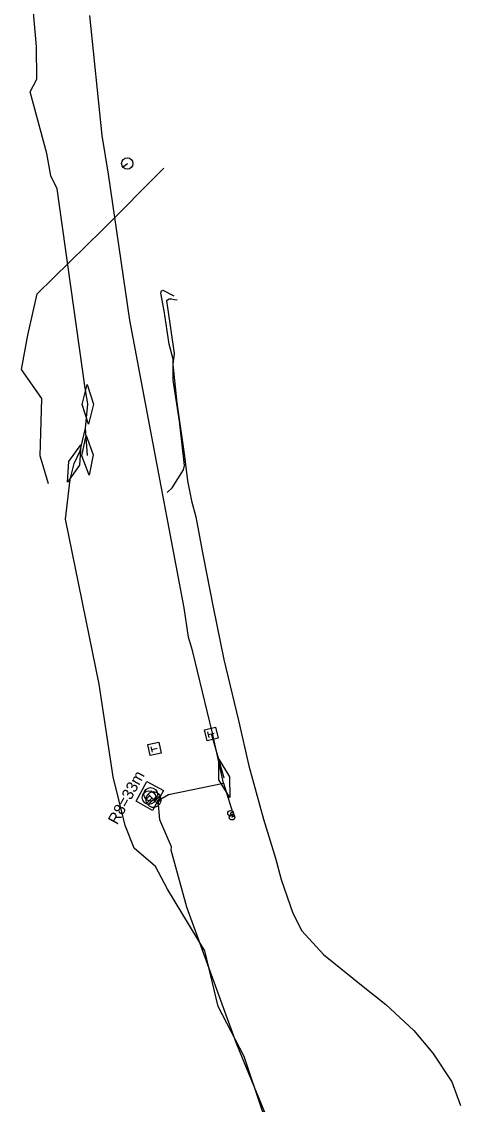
# Model space of a CAD drawing. Extents: x -748507 to -687366, y -1057342 to -1024924.
# Drawn here: x -744476.5 to -744399.1, y -1039770.3 to -1039579.2 of the extents above; entities that cross this region are included whole.
import ezdxf

# ---------------------------------------------------------------- set-up
doc = ezdxf.new("R2010")
doc.units = 0
for name, color, linetype in [('6kV - SŽDC', 7, 'Continuous'), ('DK + TKK - SŽDC', 7, 'Continuous'), ('kanalizace ČD', 7, 'Continuous'), ('PRE - NN', 7, 'Continuous'), ('Sděl MK - SŽDC', 7, 'Continuous'), ('TK+DOK_Pha Holešovice - Kralupy', 7, 'Continuous'), ('Vrstva 42', 7, 'Continuous')]:
    doc.layers.add(name, color=color, linetype=linetype)

msp = doc.modelspace()

# ---------------------------------------------------------------- linework, layer by layer
at = {"layer": '6kV - SŽDC'}
for points in [[(-744471.33, -1039606.37), (-744472.04, -1039602.45), (-744474.97, -1039591.58), (-744473.84, -1039589.36), (-744473.9, -1039583.59), (-744475.42, -1039566.22)], [(-744465.37, -1039643.47), (-744470.25, -1039608.71), (-744471.33, -1039606.37)], [(-744466.19, -1039654.94), (-744465.22, -1039650.95), (-744464.82, -1039646.7), (-744465.37, -1039643.47)], [(-744464.69, -1039650.2), (-744465.82, -1039646.74), (-744464.95, -1039643.2), (-744463.82, -1039646.66), (-744464.69, -1039650.2)], [(-744464.6, -1039659.21), (-744465.86, -1039655.8), (-744465.12, -1039652.23), (-744463.86, -1039655.65), (-744464.6, -1039659.21)], [(-744464.86, -1039655.72), (-744465.22, -1039650.95)], [(-744468.42, -1039660.44), (-744468.18, -1039656.8), (-744466.06, -1039653.84), (-744466.3, -1039657.48), (-744468.42, -1039660.44)], [(-744424.52, -1039793.8), (-744428.32, -1039785.58), (-744432.08, -1039776.07), (-744434.09, -1039771.12), (-744437.21, -1039761.81), (-744441.82, -1039752.98), (-744444.16, -1039743.14), (-744450.73, -1039732.3), (-744452.9, -1039728.3), (-744456.66, -1039725.06), (-744458.25, -1039721.03), (-744460.34, -1039712.48), (-744462.8, -1039696.08), (-744468.74, -1039666.97), (-744467.94, -1039659.97), (-744467.24, -1039657.14), (-744466.19, -1039654.94)]]:
    msp.add_lwpolyline(points, dxfattribs=at)
at = {"layer": 'DK + TKK - SŽDC'}
for p, q in [((-744439.67, -1039718.9), (-744439.57, -1039718.9)), ((-744439.43, -1039719.57), (-744439.33, -1039719.57))]:
    msp.add_line(p, q, dxfattribs=at)
for points in [[(-744447.82, -1039682.66), (-744454.1, -1039649.32), (-744457.43, -1039631.85), (-744461.19, -1039606.07), (-744462.28, -1039599.29), (-744464.47, -1039578.08)], [(-744440.86, -1039713.58), (-744442.82, -1039704.78), (-744446.35, -1039690.15), (-744447.03, -1039687.79), (-744447.82, -1039682.66)], [(-744450.03, -1039724.84), (-744452.09, -1039720.03), (-744452.43, -1039716.64), (-744450.57, -1039715.59), (-744440.86, -1039713.58)], [(-744440.86, -1039713.58), (-744439.27, -1039718.67), (-744438.94, -1039719.36)], [(-744439.27, -1039718.67), (-744439.62, -1039718.9)], [(-744438.94, -1039719.36), (-744439.38, -1039719.57)], [(-744409.27, -1039827.53), (-744414.03, -1039816.04), (-744422.5, -1039800.57), (-744424.03, -1039794.9), (-744438.59, -1039759.5), (-744447.32, -1039735.48), (-744450.1, -1039725.43), (-744450.03, -1039724.84)]]:
    msp.add_lwpolyline(points, dxfattribs=at)
for centre in [(-744439.62, -1039718.9), (-744439.38, -1039719.57)]:
    msp.add_circle(centre, 0.5, dxfattribs=at)
at = {"layer": 'kanalizace ČD'}
msp.add_lwpolyline([(-744458.62, -1039604.83), (-744457.81, -1039604.23)], dxfattribs=at)
msp.add_circle((-744457.85, -1039604.21), 1, dxfattribs=at)
at = {"layer": 'PRE - NN'}
msp.add_lwpolyline([(-744449.05, -1039628.36), (-744449.5, -1039628.26), (-744450.05, -1039628.18), (-744450.46, -1039628.15), (-744450.94, -1039628.48), (-744450.73, -1039629.65), (-744449.61, -1039637.73), (-744449.84, -1039639.66), (-744449.1, -1039646.43), (-744447.74, -1039655.87), (-744447.23, -1039660.21), (-744446.52, -1039663.73), (-744445.76, -1039666.56), (-744444.48, -1039673.5), (-744442.67, -1039682.49), (-744440.8, -1039691.78), (-744438.2, -1039702.53), (-744436.39, -1039710.5), (-744433.81, -1039719.93), (-744431.7, -1039726.82), (-744430.67, -1039730.59), (-744428.65, -1039736.51), (-744427.04, -1039739.66), (-744423.25, -1039743.84), (-744416.2, -1039749.44), (-744412.2, -1039752.66), (-744407.28, -1039757.22), (-744403.9, -1039761.23), (-744400.59, -1039766.3), (-744399.07, -1039770.48)], dxfattribs=at)
at = {"layer": 'Sděl MK - SŽDC'}
for p, q in [((-744443.38, -1039705.49), (-744443.62, -1039704.52)), ((-744443.5, -1039705), (-744442.53, -1039704.76)), ((-744453.42, -1039708.12), (-744453.64, -1039707.14)), ((-744453.53, -1039707.63), (-744452.56, -1039707.41))]:
    msp.add_line(p, q, dxfattribs=at)
for points in [[(-744450.84, -1039662.28), (-744449.95, -1039661.46), (-744447.92, -1039658.29), (-744447.73, -1039657.49), (-744448.62, -1039649.71), (-744449.78, -1039642.45), (-744449.74, -1039638.72), (-744450.44, -1039636.08), (-744451.34, -1039630.19), (-744451.92, -1039627.09), (-744451.83, -1039626.68), (-744451.56, -1039626.57), (-744449.66, -1039627.56)], [(-744443.75, -1039706.09), (-744444.23, -1039704.15), (-744442.28, -1039703.67), (-744441.81, -1039705.62), (-744443.75, -1039706.09)], [(-744440.75, -1039712.72), (-744443.02, -1039704.88)], [(-744453.8, -1039708.72), (-744454.24, -1039706.77), (-744452.29, -1039706.32), (-744451.85, -1039708.28), (-744453.8, -1039708.72)], [(-744439.78, -1039716.08), (-744441.71, -1039713), (-744441.72, -1039709.36), (-744439.79, -1039712.44), (-744439.78, -1039716.08)]]:
    msp.add_lwpolyline(points, dxfattribs=at)
at = {"layer": 'TK+DOK_Pha Holešovice - Kralupy'}
for p, q in [((-744454.94, -1039715.34), (-744454.91, -1039715.31)), ((-744454.58, -1039716.47), (-744453.91, -1039715.8)), ((-744454.42, -1039717.12), (-744453.51, -1039716.2)), ((-744452.43, -1039716.64), (-744453.23, -1039716.47)), ((-744453.01, -1039716.7), (-744452.08, -1039715.77)), ((-744452.6, -1039717.1), (-744451.89, -1039716.39)), ((-744452.28, -1039715.51), (-744452.28, -1039715.51)), ((-744452.28, -1039715.51), (-744452.28, -1039715.51)), ((-744454.2, -1039717.42), (-744454.2, -1039717.42)), ((-744454.2, -1039717.42), (-744454.2, -1039717.42)), ((-744452.27, -1039717.42), (-744452.27, -1039717.42))]:
    msp.add_line(p, q, dxfattribs=at)
for points in [[(-744424.03, -1039794.9), (-744438.59, -1039759.5), (-744447.32, -1039735.48), (-744450.1, -1039725.43), (-744450.03, -1039724.84), (-744452.09, -1039720.03), (-744452.43, -1039716.64), (-744450.57, -1039715.59), (-744440.86, -1039713.58), (-744442.82, -1039704.78), (-744446.35, -1039690.15), (-744447.03, -1039687.79), (-744447.82, -1039682.66), (-744454.1, -1039649.32), (-744457.43, -1039631.85), (-744461.19, -1039606.07), (-744462.28, -1039599.29), (-744464.47, -1039578.08)], [(-744450.03, -1039724.84), (-744452.09, -1039720.03), (-744452.43, -1039716.64), (-744450.57, -1039715.59), (-744440.86, -1039713.58), (-744442.82, -1039704.78), (-744446.35, -1039690.15), (-744447.03, -1039687.79), (-744447.82, -1039682.66), (-744454.1, -1039649.32), (-744457.43, -1039631.85), (-744461.19, -1039606.07), (-744462.28, -1039599.29), (-744464.47, -1039578.08)], [(-744454.18, -1039715.51), (-744453.24, -1039716.47), (-744454.2, -1039717.42)], [(-744452.28, -1039715.51), (-744453.23, -1039716.47), (-744452.27, -1039717.42)], [(-744409.27, -1039827.53), (-744414.03, -1039816.04), (-744422.5, -1039800.57), (-744424.03, -1039794.9), (-744438.59, -1039759.5), (-744447.32, -1039735.48), (-744450.1, -1039725.43), (-744450.03, -1039724.84)]]:
    msp.add_lwpolyline(points, dxfattribs=at)
msp.add_lwpolyline([(-744456.3, -1039716.78), (-744454.38, -1039713.29), (-744451.47, -1039714.89), (-744453.39, -1039718.39)], close=True, dxfattribs=at)
for centre in [(-744454.03, -1039716.12), (-744453.73, -1039715.54)]:
    msp.add_circle(centre, 1.2, dxfattribs=at)
for centre, start, end in [((-744453.23, -1039716.47), 45.4773, 134.8434), ((-744453.24, -1039716.47), 134.5251, 224.7621), ((-744453.23, -1039716.47), 315.2403, 45.4773), ((-744453.24, -1039716.47), 224.7634, 315.5529)]:
    msp.add_arc(centre, 1.35, start, end, dxfattribs=at)
at = {"layer": 'Vrstva 42'}
msp.add_lwpolyline([(-744471.76, -1039660.73), (-744473.22, -1039655.82), (-744473.16, -1039653.79), (-744472.92, -1039645.68), (-744476.5, -1039640.6), (-744475.39, -1039634.5), (-744473.79, -1039627.24), (-744462.23, -1039615.9), (-744451.39, -1039605.05)], dxfattribs=at)

# ---------------------------------------------------------------- texts
at = {"layer": 'TK+DOK_Pha Holešovice - Kralupy'}
msp.add_text('R8=33m', height=2, rotation=61.1542, dxfattribs=at).set_placement((-744459.63, -1039721.04))

doc.saveas('drawing.dxf')
